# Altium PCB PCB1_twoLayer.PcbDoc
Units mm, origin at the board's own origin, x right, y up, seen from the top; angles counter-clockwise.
Board outline 70 x 67 mm, 2 copper layers (Top Layer, Bottom Layer), stack 1.569 mm thick; 44 components, 52 nets, 201 pads, 36 vias.
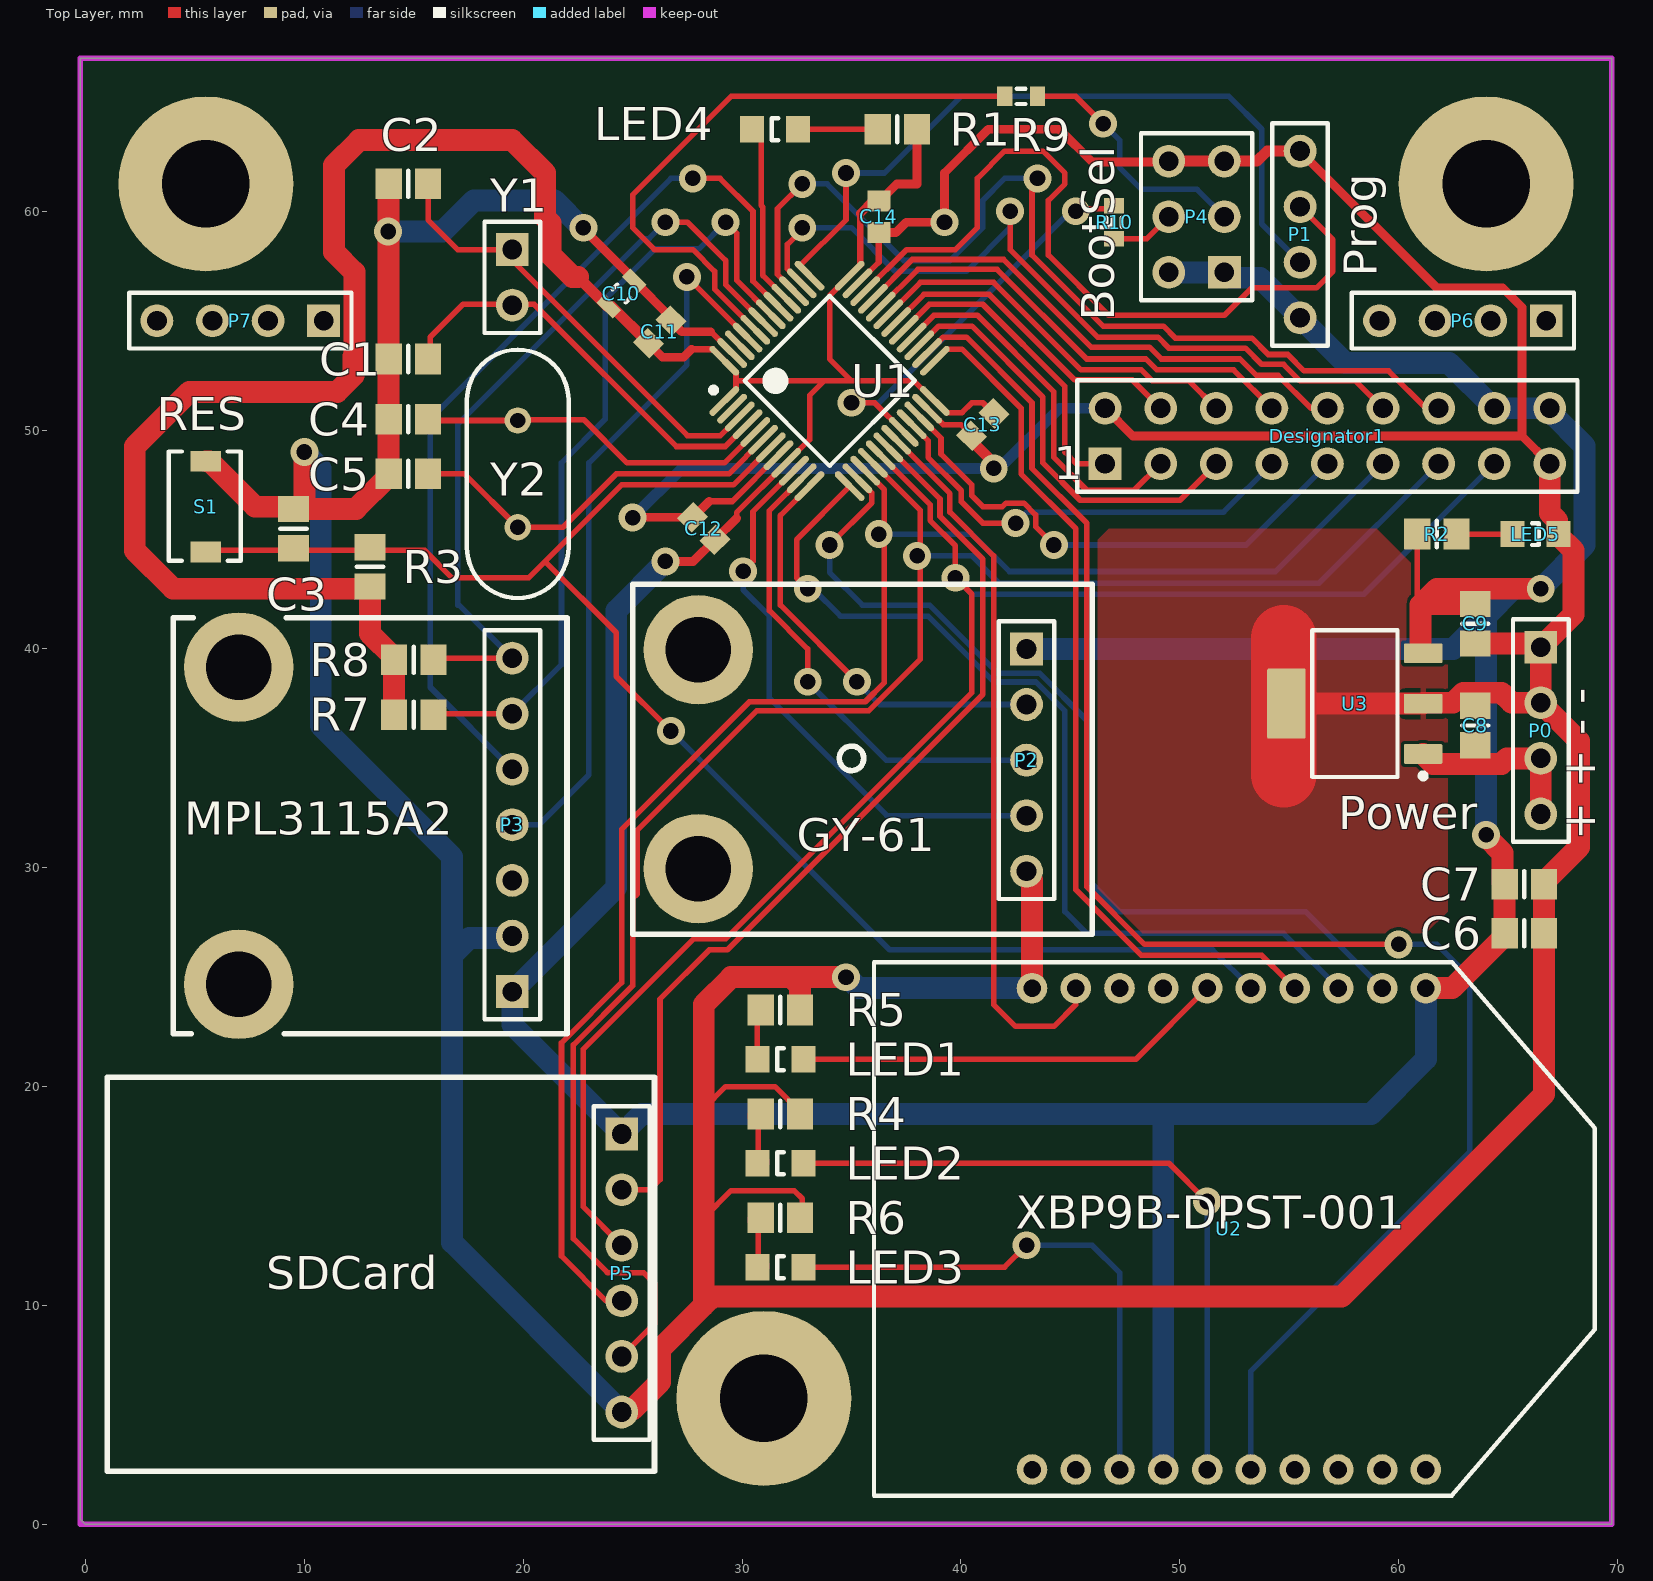
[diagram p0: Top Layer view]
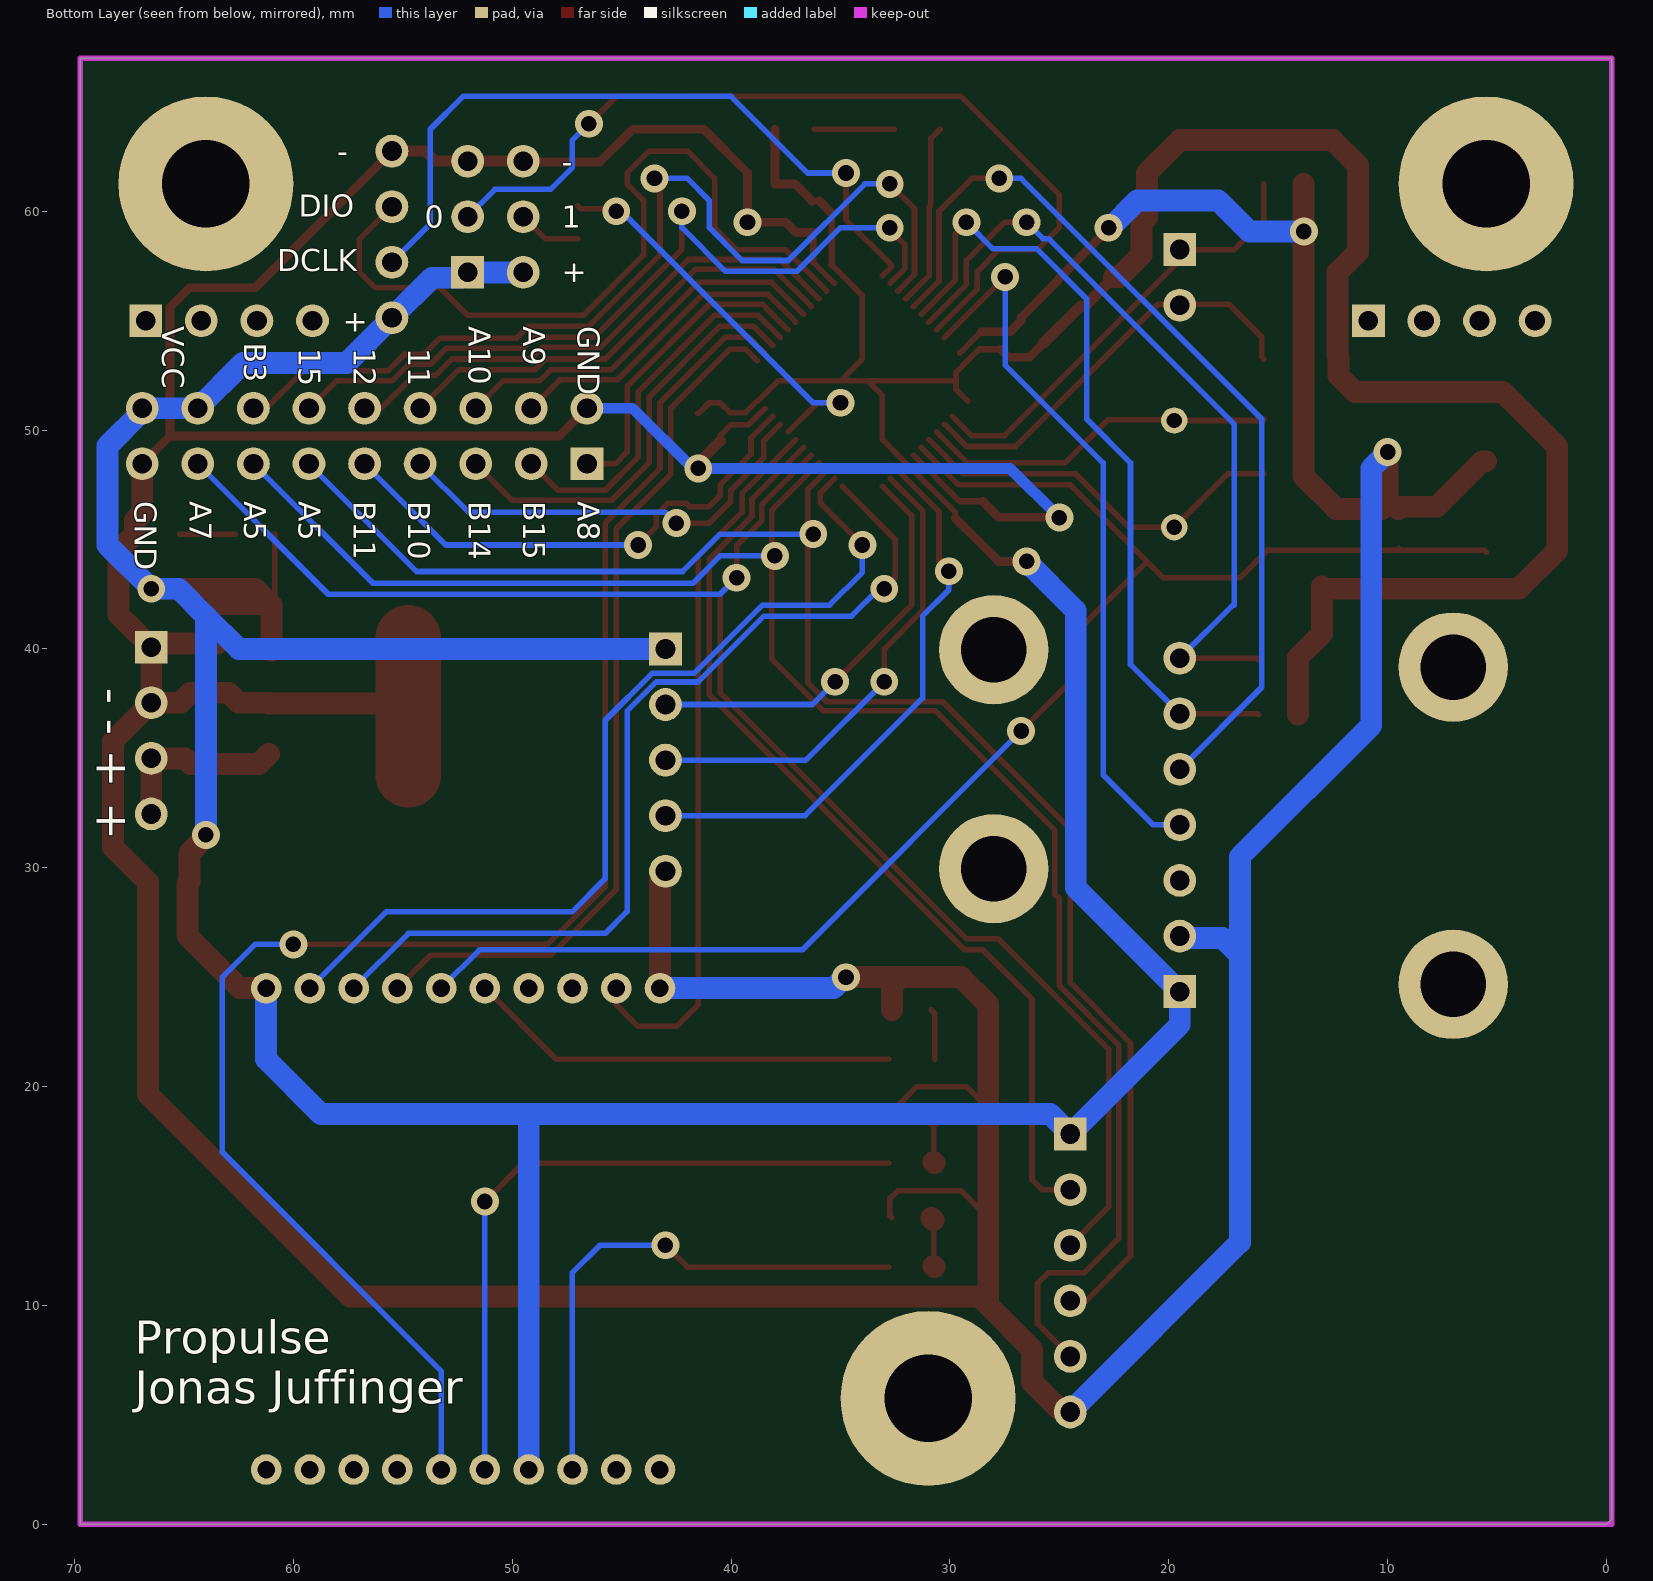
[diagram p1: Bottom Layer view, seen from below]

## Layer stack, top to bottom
Top Solder: solder mask 0.0254, SM-001, Dk 4
Top Layer: signal copper 0.035
Dielectric 1: core 1.4986, Core-043, Dk 4.3
Bottom Layer: signal copper 0.035
Bottom Solder: solder mask 0.0254, SM-001, Dk 4

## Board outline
0,0 -0.25,0.25 -0.25,67 69.75,67 69.75,0

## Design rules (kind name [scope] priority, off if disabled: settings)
Clearance [All] p1: gap=0.152 ignorepadtopadclearanceinfootprint=FALSE
HoleSize [All] p1: absolutevalues=TRUE maxlimit=6 minlimit=0.025 maxpercent=80.000 minpercent=20.000
PolygonConnect [All] p1: connectstyle=Relief reliefconductorwidth=0.254 reliefentries=4 polygonreliefangle="90 Angle" airgapwidth=0.254
RoutingVias [All] p1: holewidth=0.711 width=1.27 viastyle="Through Hole" minholewidth=0.711 minwidth=1.27 maxholewidth=0.711 maxwidth=1.27
SilkToSilkClearance [All] p1: silktosilkclearance=0
SilkToSolderMaskClearance [IsPad] p1: minsilkscreentomaskgap=0.15 clearancetoexposedcopper=TRUE
SolderMaskExpansion [All] p1: expansion=0.102
Width [All] p1: maxlimit=10 minlimit=0.254 preferedwidth=0.254
27 further rules are at their usual default settings.

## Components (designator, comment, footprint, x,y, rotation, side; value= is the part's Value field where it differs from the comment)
C1 "Cap" 6-0805_N 14.75,53.25 r180 top value=12pF
C2 "Cap" 6-0805_N 14.75,61.25 r180 top value=12pF
C3 "Cap" 6-0805_N 9.5,45.5 r270 top value=100nF
C4 "Cap" 6-0805_N 14.75,50.5 r0 top value=18pF
C5 "Cap" 6-0805_N 14.75,48 r0 top value=18pF
C6 "Cap" 6-0805_N 65.75,27 r180 top value=100nF
C7 "Cap" 6-0805_N 65.75,29.25 r180 top value=1µF
C8 "Cap" 6-0805_N 63.5,36.5 r270 top value=10uF
C9 "Cap" 6-0805_N 63.5,41.15 r90 top value=10uF
C10 "1 µF" CAPC1609X100X15NL20 24.487,56.237 r225 top
C11 "100 nF" SAMS-C0603-2_M 26.237,54.487 r45 top
C12 "100 nF" SAMS-C0603-2_M 28.25,45.5 r135 top
C13 "100 nF" SAMS-C0603-2_M 41,50.25 r225 top
C14 "100 nF" SAMS-C0603-2_M 36.25,59.75 r270 top
Designator1 "Header 9X2" HDR2X9 46.59,48.46 r0 top (schematic designator "Designator 1")
LED1 "150080SS75000" 0805_A 31.75,21.25 r0 top
LED2 "150080SS75000" 0805_A 31.75,16.5 r0 top
LED3 "150080SS75000" 0805_A 31.75,11.75 r0 top
LED4 "150080SS75000" 0805_A 31.5,63.75 r0 top
LED5 "150080SS75000" 0805_A 66.25,45.25 r180 top
P0 "Power" HDR1X4#1 66.5,40.08 r270 top
P1 "Prog" HDR1X4#2 55.5,55.13 r90 top
P2 "GY-61" HDR1X5 43,40 r270 top
P3 "MPL3115A2" HDR1X7 19.5,24.34 r90 top
P4 "BootSel" HDR2X3 52.04,57.21 r90 top
P5 "SDCard" HDR1X6 24.5,17.83 r270 top
P6 "Breadboard Mount" HDR1X4#1 66.75,55 r180 top
P7 "Breadboard Mount" HDR1X4#1 10.88,55 r180 top
R1 "Res1" 6-0805_N 37.1,63.75 r0 top value=1K
R2 "Res1" 6-0805_N 61.75,45.25 r180 top value=1K
R3 "Res1" 6-0805_N 13,43.75 r270 top value=10k
R4 "Res1" 6-0805_N 31.75,18.75 r180 top value=1K
R5 "Res1" 6-0805_N 31.75,23.5 r180 top value=1K
R6 "Res1" 6-0805_N 31.75,14 r180 top value=1K
R7 "Res1" 6-0805_N 15,37 r180 top value=2K
R8 "Res1" 6-0805_N 15,39.5 r180 top value=2K
R9 "Res3" J1-0603 42.75,65.25 r0 top value=100K
R10 "Res3" J1-0603 47,59.5 r90 top value=100K
S1 "RES" "SWITCH- TL1015AF160QG" 5.5,46.5 r90 top
U1 "STM32F103C8T6" STM-LQFP48_N 34,52.25 r45 top
U2 "XBP9B-DPST-001" DIP2200W51P200L3294H279Q20P 52.5,13.5 r270 top
U3 "TL1963A-33DCYR" DCY0004A_N 58,37.5 r180 top
Y1 "XTAL" HDR1X2 19.5,58.25 r270 top
Y2 "FOXSLF/120-20" FOX-FOXSLF-2_V 19.75,48 r270 top

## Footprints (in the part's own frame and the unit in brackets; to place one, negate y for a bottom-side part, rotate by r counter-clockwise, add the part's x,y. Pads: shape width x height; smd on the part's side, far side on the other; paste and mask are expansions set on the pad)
6-0805_N [mm] "Chip Resistor, Body 2.0x1.2mm, IPC Medium Density"
  rect 1.2x1.4 smd: 1(-0.9,0) 2(0.9,0)
  silkscreen extent 0,-0.6 0,0.6, body extent -1.07,-0.7 1.07,0.7, height 0.7
0805_A [mm] "Chip LED, 2-Leads, Body 2.0x1.3mm, IPC Medium Density"
  rect 1.1x1.2 smd: 1(-1.05,0) 2(1.05,0)
  silkscreen extent -0.15,-0.5 0.15,0.5, body extent -1,-0.62 1,0.63, height 0.68
CAPC1609X100X15NL20 [mm] "Chip Capacitor, 2-Leads, Body 1.60x0.85mm, IPC Medium Density"
  rect 0.55x1.05 smd: 1(-0.825,0) 2(0.825,0)
  silkscreen extent -0.15,-0.42 0.15,0.42, body extent -0.9,-0.53 0.9,0.53, height 1
DCY0004A_N [mm] "SOT223, 4-Leads, Body 6.7x3.7mm, Pitch 2.3mm, IPC Medium Density"
  rrect11% 1.75x0.9 smd: 1(-3.125,2.3) 2(-3.125,0) 3(-3.125,-2.3)
  rrect6% 1.75x3.2 smd: 4(3.125,0)
  silkscreen extent -3.25,-3.35 1.95,3.42, body extent -3.5,-3.25 3.5,3.25, height 1.62
DIP2200W51P200L3294H279Q20P [mm]
  round 1.4 hole 0.8: 1(-11,8.75) 2(-11,6.75) 3(-11,4.75) 4(-11,2.75) 5(-11,0.75) 6(-11,-1.25) 7(-11,-3.25) 8(-11,-5.25) 9(-11,-7.25) 10(-11,-9.25) 11(11,-9.25) 12(11,-7.25) 13(11,-5.25) 14(11,-3.25) 15(11,-1.25) 16(11,0.75) 17(11,2.75) 18(11,4.75) 19(11,6.75) 20(11,8.75)
  silkscreen extent -12.19,-16.47 12.19,16.47, body extent -12.18,-16.77 12.2,16.17, height 4.09
FOX-FOXSLF-2_V [mm] "THD, 2-Leads, Body 11.35x4.65mm, Pitch 4.88mm"
  round 1.2 hole 0.7: 1(-2.44,0) 2(2.44,0)
  silkscreen extent -5.68,-2.32 5.68,2.32, body extent -5.67,-2.32 5.68,2.32, height 3.6
HDR1X2 [mm] "Connector; Header; 2 Position"
  rect 1.5x1.5 hole 0.9: 1(0,0)
  round 1.5 hole 0.9: 2(2.54,0)
  silkscreen extent -1.27,-1.27 3.81,1.27
HDR1X4#1 [mm] "Connector; Header; 4 Position"
  rect 1.5x1.5 hole 0.9: 1(0,0)
  round 1.5 hole 0.9: 2(2.54,0) 3(5.08,0) 4(7.62,0)
  silkscreen extent -1.27,-1.27 8.89,1.27
HDR1X4#2 [mm] "Connector; Header; 4 Position"
  round 1.5 hole 0.9: 1(0,0) 2(2.54,0) 3(5.08,0) 4(7.62,0)
  silkscreen extent -1.27,-1.27 8.89,1.27
HDR1X5 [mm] "Connector; Header; 5 Position"
  rect 1.5x1.5 hole 0.9: 1(0,0)
  round 1.5 hole 0.9: 2(2.54,0) 3(5.08,0) 4(7.62,0) 5(10.16,0)
  silkscreen extent -1.27,-1.27 11.43,1.27
HDR1X6 [mm] "Connector; Header; 6 Position"
  rect 1.5x1.5 hole 0.9: 1(0,0)
  round 1.5 hole 0.9: 2(2.54,0) 3(5.08,0) 4(7.62,0) 5(10.16,0) 6(12.7,0)
  silkscreen extent -1.27,-1.27 13.97,1.27
HDR1X7 [mm] "Connector; Header; 7 Position"
  rect 1.5x1.5 hole 0.9: 1(0,0)
  round 1.5 hole 0.9: 2(2.54,0) 3(5.08,0) 4(7.62,0) 5(10.16,0) 6(12.7,0) 7(15.24,0)
  silkscreen extent -1.27,-1.27 16.51,1.27
HDR2X3 [mm] "Connector; Header; 3x2 Position"
  rect 1.5x1.5 hole 0.9: 1(0,0)
  round 1.5 hole 0.9: 2(0,2.54) 3(2.54,0) 4(2.54,2.54) 5(5.08,0) 6(5.08,2.54)
  silkscreen extent -1.27,-1.27 6.35,3.81
HDR2X9 [mm] "Connector; Header; 9x2 Position"
  rect 1.5x1.5 hole 0.9: 1(0,0)
  round 1.5 hole 0.9: 2(0,2.54) 3(2.54,0) 4(2.54,2.54) 5(5.08,0) 6(5.08,2.54) 7(7.62,0) 8(7.62,2.54) 9(10.16,0) 10(10.16,2.54) 11(12.7,0) 12(12.7,2.54) 13(15.24,0) 14(15.24,2.54) 15(17.78,0) 16(17.78,2.54) 17(20.32,0) 18(20.32,2.54)
  silkscreen extent -1.27,-1.27 21.59,3.81
J1-0603 [mm] "Chip Resistor, Body 1.6x0.8mm, IPC High Density"
  rect 0.7x0.9 smd: 1(-0.75,0) 2(0.75,0)
  silkscreen extent -0.2,-0.35 0.2,0.35, body extent -0.85,-0.48 0.85,0.48, height 0.9
SAMS-C0603-2_M [mm] "Chip Capacitor, 2-Leads, Body 1.70x0.90mm, IPC Low Density"
  rect 0.95x1.05 smd: 1(-0.725,0) 2(0.725,0)
  body extent -0.85,-0.45 0.85,0.45, height 0.9
STM-LQFP48_N [mm] "QFP, 48-Leads, Body 7x7mm, Pitch 0.5mm, IPC Medium Density"
  oval 1.8x0.3 smd: 1(-4.05,2.75) 2(-4.05,2.25) 3(-4.05,1.75) 4(-4.05,1.25) 5(-4.05,0.75) 6(-4.05,0.25) 7(-4.05,-0.25) 8(-4.05,-0.75) 9(-4.05,-1.25) 10(-4.05,-1.75) 11(-4.05,-2.25) 12(-4.05,-2.75) 25(4.05,-2.75) 26(4.05,-2.25) 27(4.05,-1.75) 28(4.05,-1.25) 29(4.05,-0.75) 30(4.05,-0.25) 31(4.05,0.25) 32(4.05,0.75) 33(4.05,1.25) 34(4.05,1.75) 35(4.05,2.25) 36(4.05,2.75)
  oval 0.3x1.8 smd: 13(-2.75,-4.05) 14(-2.25,-4.05) 15(-1.75,-4.05) 16(-1.25,-4.05) 17(-0.75,-4.05) 18(-0.25,-4.05) 19(0.25,-4.05) 20(0.75,-4.05) 21(1.25,-4.05) 22(1.75,-4.05) 23(2.25,-4.05) 24(2.75,-4.05) 37(2.75,4.05) 38(2.25,4.05) 39(1.75,4.05) 40(1.25,4.05) 41(0.75,4.05) 42(0.25,4.05) 43(-0.25,4.05) 44(-0.75,4.05) 45(-1.25,4.05) 46(-1.75,4.05) 47(-2.25,4.05) 48(-2.75,4.05)
  silkscreen extent -4.17,-2.75 2.75,3.57, body extent -3.5,-3.5 3.5,3.5, height 1.6
"SWITCH- TL1015AF160QG" [mm]
  rect 0.95x1.4 smd: 1(-2.075,0) 2(2.075,0)
  silkscreen extent -2.47,-1.6 2.53,1.7, body extent -2.26,-1.4 2.24,1.5, height 2.05

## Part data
C1 C2 C3 C4 C5 C6 C7 C8 C9: "Capacitor"
C10: library part CMP-2006-00184-1, Manufacturer="AVX Interconnect / Elco", Part Number=TACL105K010XTA
C11 C12 C13 C14: library part CMP-2000-05332-1, "Multi-layer Ceramic Capacitor, -55 to 125 degC, 2-Pin SMD (0603), RoHS, Tape and Reel", Capacitance=0.1µF, Case Size/Dimension=0603, Dielectric=X7R, Manufacturer="Samsung Electro-Mechanics", Rated Voltage=50V, Tolerance (%)=±10%
Designator1: "Header, 9-Pin, Dual row"
LED1 LED2 LED3 LED4 LED5: library part CMP-1426-00010-1, "SMD mono-color Chip LED, WL-SMCW, Super Red", Color="Super Red", Manufacturer="Wuerth Elektronik"
P0 P6 P7: library part "Header 4", "Header, 4-Pin"
P1: library part "Header 4", "Programming header like on Blue Pill"
P2: library part "Header 5", "GY-61 breakout board"
P3: library part "Header 7", "Adafruit MPL3115A2 breakout board"
P4: library part "Header 3X2", "Header, 3-Pin, Dual row"
P5: library part "Header 6", "Header, 6-Pin"
R1 R2 R3 R4 R5 R6 R7 R8 R9 R10: "Resistor"
S1: library part SWITCH_2PIN, Supplier Part Number 1=2292962
U1: "ARM Cortex-M3 32-bit MCU, 64 KB Flash, 20 KB Internal RAM, 37 I/Os, 48-pin LQFP, -40 to 85 degC, Tray", I/Os (High Current)=37, Operating Frequency(F) (Processor speed) (MHz)=72, Supplier Part Number 1=497-6063-ND, Supply Voltage(Vcc) min (V)=2
U2: "XBee-PRO 900HP _S3B_ Point2Multipoint, 900MHz, 250mW, RPSMA, 10Kbps", Package="Module Digi International"
U3: library part CMP-0395-00535-2, "Single Output Low Noise LDO, 1.5 A, Fixed 3.3 V Output, 2.1 to 20 V Input, 4-pin SOT-223 (DCY), -40 to 125 degC, Green (RoHS & no Sb/Br)", Manufacturer="Texas Instruments"
Y1: "Crystal Oscillator"
Y2: library part CMP-1749-00004-1, "Resistance Weld Thru-Hole Crystal, 12 MHz, +/-30 ppm, -20 to 70 degC, 2-Pin THD, RoHS, Bulk", Case\Package=TO-251-3, Input Capacitance="350 pF", Max Operating Temperature="150 degC", Max Power Dissipation="2.5 W", Min Operating Temperature="-55 degC", Package Quantity=70

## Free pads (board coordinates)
  round 5 hole 3: 1(28,29.96) 1(28,39.96) 2(7,24.67) 2(7,39.17)
  round 8 hole 4: 3(5.5,61.25) 3(31,5.75) 3(64,61.25)

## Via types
v1: diameter 1.27, hole 0.711, Top Layer to Bottom Layer, 36 vias

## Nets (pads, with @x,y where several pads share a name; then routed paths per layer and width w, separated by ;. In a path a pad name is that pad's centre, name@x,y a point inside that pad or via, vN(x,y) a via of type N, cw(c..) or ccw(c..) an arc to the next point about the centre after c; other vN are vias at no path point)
AccX: P2.2 U1.12 | length 19.1
  Top Layer w0.254: U1.12 33.081,47.429 31.75,46.098 31.75,42 v1(35.25,38.5)
  Bottom Layer w0.254: v1(35.25,38.5) 36.29,37.46 P2.2
AccY: P2.3 U1.11 | length 22.1
  Top Layer w0.254: U1.11 31.25,46.318 31.25,41.75 33,40 v1(33,38.5)
  Bottom Layer w0.254: v1(33,38.5) 36.58,34.92 P2.3
AccZ: P2.4 U1.10 | length 25.8
  Top Layer w0.254: v1(30.047,43.547) 30.5,44 30.5,46.275 U1.10
  Bottom Layer w0.254: v1(30.047,43.547) 30.047,42.703 31.25,41.5 31.25,37.75 36.62,32.38 P2.4
BaroInt1: P3.5 U1.41 | length 42.3
  Top Layer w0.254: v1(27.75,61.5) 29,61.5 30.5,60 30.5,56.811 U1.41
  Bottom Layer w0.254: P3.5 15.75,38.25 15.75,50.5 26.75,61.5 v1(27.75,61.5)
BaroInt2: P3.4 U1.45 | length 33
  Top Layer w0.254: v1(27.482,57) U1.45
  Bottom Layer w0.254: P3.4 20.71,31.96 23,34.25 23,48.5 27.482,52.982 v1(27.482,57)
BOOT0: R9.1 U1.44 | length 28.4
  Top Layer w0.254: U1.44 28.75,56.439 28.75,57.25 27.75,58.25 26,58.25 25,59.25 25,60.75 29.5,65.25 R9.1
BOOT1: R10.2 U1.20 | length 18.7
  Top Layer w0.254: v1(35,51.25) 36.061,51.25 U1.20 ; v1(45.25,60) 45.375,60.125 46.875,60.125 R10.2
  Bottom Layer w0.254: v1(35,51.25) 36.25,51.25 45,60 v1(45.25,60)
DCLK: P1.2 U1.37 | length 33.6
  Top Layer w0.254: U1.37 32.655,57.484 32.655,57.514 34.75,59.609 v1(34.75,61.75)
  Bottom Layer w0.254: v1(34.75,61.75) 36.5,61.75 40,65.25 52.25,65.25 53.75,63.75 53.75,59.42 P1.2
DIO: P1.3 U1.34 | length 36.1
  Top Layer w0.254: U1.34 37.525,58.25 39.75,58.25 40.75,59.25 40.75,61.5 42,62.75 43.75,62.75 44.75,61.75 44.75,61.25 44,60.5 44,58 46.75,55.25 52.042,55.25 53.292,56.5 56.25,56.5 57,57.25 57,58.71 P1.3
GND: C1.2 C2.2 C3.1 C4.1 C5.1 C6.1 C7.1 C8.1 C9.1 C10.1 C11.2 C12.2 C13.2 C14.2 Designator1.2 Designator1.17 LED5.1 P0.1 P0.2 P1.4 P2.5 P3.2 P4.5 P4.6 P5.6 R4.1 R5.1 R6.1 S1.2 U1.8 U1.23 U1.35 U1.47 U2.10 U3.2 U3.4 | length 350
  Top Layer w0.254: v1@22.75,59.196 v1(22.75,59.25) ; P5.6 P5.6@24.614,5.244 ; v1(25,46) v1@25.013,46.013 ; C10.1 C10.1@25.071,56.875 ; C11.2 C11.2@26.75,55.141 ; C12.2 C12.2@27.763,46.013 ; 28.25,14 29.5,15.25 32.378,15.25 32.75,14.878 32.75,14.1 R6.1 ; 28.25,19 29.25,20 31.5,20 32.65,18.85 R4.1 ; 28.568,54.5 U1.47 ; 29.561,46.75 U1.8 ; U1.35 36.25,57.682 ; U1.23@38.442,50.977 U1.23 38.467,50.977 39.194,50.25 40,50.25 40.487,49.763 C13.2 C13.2@40.487,49.513 ; U3.2 U3.2@61.165,37.54 ; C7.1 C7.1@66.65,29.35 ; LED5.1@67.25,45.2 LED5.1@67.3,45.2
  Top Layer w0.3: 28.5,46.75 29.561,46.75 ; 36.25,57.682 C14.2
  Top Layer w0.4: v1@22.75,59.196 C10.1@25.071,56.875 ; v1@25.013,46.013 C12.2 ; C10.1 C11.2@26.75,55.141 ; C11.2 27.25,54.5 28.568,54.5 ; C12.2@27.763,46.013 28.5,46.75 ; C14.2 37.025,59.025 37.5,59.5 v1(39.25,59.5) 39.25,61.75 41.25,63.75 44.5,63.75 46,62.25 49.46,62.25 P4.6 ; Designator1.2 47.86,49.73 65.64,49.73 ; P1.4 61.75,56.5 64.75,56.5 65.64,55.61 65.64,49.73 ; Designator1.17 65.64,49.73
  Top Layer w0.5: C3.1 C3.1@9.5,46.75 ; v1(13.825,59.075) v1@13.838,59.063 ; C1.2@13.838,53.263 C1.2 ; C13.2@40.487,49.513 41.5,48.5 v1(41.5,48.25) ; P4.6 P4.5 53.54,62.29 54,62.75 P1.4
  Top Layer w1: S1.2 5.675,48.575 7.75,46.5 9.4,46.5 C3.1 ; v1(10,49) 10,46.65 10.25,46.4 12.35,46.4 13.85,47.9 C5.1 C4.1 C1.2 ; v1(13.825,59.075) 13.838,59.088 13.838,61.238 C2.2 ; C1.2@13.838,53.263 v1@13.838,59.063 ; P5.6@24.614,5.244 24.994,5.244 26.25,6.5 26.25,8 28.25,10 ; R5.1 32.65,24.6 32.25,25 ; v1(34.75,25) 32.25,25 ; P2.5 43,29.705 43.25,29.455 U2.10 ; U3.4 U3.2 ; U3.2@61.125,37.54 61.165,37.54 62.499,37.54 62.959,38 64.706,38 65.166,37.54 P0.2 ; C9.1 P0.1@66.5,40.25 ; C7.1 C6.1 66.65,19.65 57.402,10.402 28.652,10.402 28.25,10 ; C7.1@66.65,29.35 68.25,30.95 68.25,35.79 P0.2 ; Designator1.17 66.91,46.21 67.25,45.87 67.25,45.3 LED5.1 LED5.1@67.25,45.2 ; LED5.1@67.3,45.2 68,44.5 68,41.58 P0.1 P0.2 ; 28.25,10 28.25,14 28.25,19 28.25,23.75 29.5,25 32.25,25
  Top Layer w3: 54.75,34.25 54.75,40.5
  Bottom Layer w0.5: v1(25,46) 27.25,48.25 v1(41.5,48.25) 41.75,48.25 44.5,51 Designator1.2
  Bottom Layer w1: v1(10,49) 10.75,48.25 10.75,36.5 16.75,30.5 16.75,26 17.534,26.784 19.404,26.784 P3.2 ; v1(13.825,59.075) 16.325,59.075 17.75,60.5 21.427,60.5 22.677,59.25 v1(22.75,59.25) ; 16.75,25.914 16.75,12.88 P5.6 ; v1(34.75,25) 34.823,25 35.323,24.5 U2.10
MISO: Designator1.13 P5.5 U1.16 | length 81
  Top Layer w0.254: P5.5 26,9.17 26,11 25.5,11.5 23.852,11.5 22.296,13.056 22.296,21.904 25,24.608 25,28.588 25.221,28.809 25.221,31.721 30.679,37.179 35.797,37.179 38.138,39.52 38.138,46.344 U1.16
  Bottom Layer w0.254: v1(38,44.25) 40.5,44.25 41.75,43 56.37,43 Designator1.13
MOSI: Designator1.15 P5.3 U1.17 | length 74.2
  Top Layer w0.254: P5.3 22.75,14.5 22.75,21.716 27.784,26.75 29.25,26.75 40.5,38 40.5,42.5 v1(39.75,43.25) 39.75,44.716 38.592,45.874 38.592,46.597 U1.17
  Bottom Layer w0.254: v1(39.75,43.25) 40.5,42.5 58.41,42.5 Designator1.15
NetC8_2: C8.2 P0.3 P0.4 U3.1 | length 8.2
  Top Layer w1: U3.1 61.575,34.75 64.7,34.75 64.95,35 P0.3 P0.4
NetLED1_1: LED1.1 R5.2 | length 2.3
  Top Layer w0.254: LED1.1 30.7,23.35 R5.2
NetLED1_2: LED1.2 U2.6 | length 19.8
  Top Layer w0.254: LED1.2 48,21.25 U2.6
NetLED2_1: LED2.1 R4.2 | length 2.3
  Top Layer w0.254: LED2.1@30.75,16.55 R4.2@30.75,18.65
  Top Layer w1: LED2.1 LED2.1@30.75,16.55 ; R4.2@30.75,18.65 R4.2
NetLED2_2: LED2.2 U2.15 | length 31.4
  Top Layer w0.254: LED2.2 49.5,16.5 v1(51.25,14.75)
  Bottom Layer w0.254: U2.15 v1(51.25,14.75)
NetLED3_1: LED3.1 R6.2 | length 2.3
  Top Layer w0.254: LED3.1@30.75,11.8 R6.2@30.75,13.9
  Top Layer w1: LED3.1 LED3.1@30.75,11.8 ; R6.2@30.75,13.9 R6.2
NetLED3_2: LED3.2 U2.13 | length 24.4
  Top Layer w0.254: LED3.2 42,11.75 v1(43,12.75)
  Bottom Layer w0.254: v1(43,12.75) 46,12.75 47.25,11.5 U2.13
NetLED4_2: LED4.2 R1.1 | length 3.7
  Top Layer w0.254: LED4.2 R1.1
NetLED5_2: LED5.2 R2.1 | length 2.6
  Top Layer w0.254: R2.1 LED5.2
NetP4_3: P4.3 R9.2 | length 11.6
  Top Layer w0.254: R9.2 45.25,65.25 v1(46.5,64)
  Bottom Layer w0.254: v1(46.5,64) 47.25,63.25 47.25,62 48.25,61 50.79,61 P4.3
NetP4_4: P4.4 R10.1 | length 2.9
  Top Layer w0.254: R10.1 48.5,58.75 P4.4
NRST: C3.2 R3.1 S1.1 U1.7 U2.5 | length 70.5
  Top Layer w0.254: S1.1 5.575,44.5 C3.2@9.4,44.5 ; C3.2 C3.2@9.4,44.5 ; v1(26.75,36.25) 24.25,38.75 24.25,40.75 21,44 ; U1.7 29.604,47.5 24.5,47.5 21,44 ; C3.2@9.4,44.5 9.5,44.5 15.5,44.5 16.75,43.25 20.25,43.25 21,44
  Bottom Layer w0.254: v1(26.75,36.25) 36.75,26.25 51.5,26.25 U2.5
PA8: Designator1.1 U1.29 | length 14.5
  Top Layer w0.254: U1.29 38.561,55.75 41,55.75 44.75,52 44.75,49 45.29,48.46 Designator1.1
PA11: Designator1.8 U1.32 | length 21.2
  Top Layer w0.254: U1.32 38.031,57.342 41.658,57.342 45.75,53.25 48.454,53.25 48.954,52.75 52.46,52.75 Designator1.8
PA12: Designator1.10 U1.33 | length 24.3
  Top Layer w0.254: U1.33 37.778,57.796 41.954,57.796 45.954,53.796 48.612,53.796 49.158,53.25 52.75,53.25 53.5,52.5 54.5,52.5 56,51 Designator1.10
PA15: Designator1.12 U1.38 | length 36.8
  Top Layer w0.254: U1.38 32.727,56.717 32.073,57.371 32.073,58.49 32.75,59.166 v1(32.75,59.25) ; v1(42.25,60) 42.25,58.25 46.25,54.25 49,54.25 49.5,53.75 53,53.75 53.75,53 54.75,53 55.5,52.25 58.04,52.25 Designator1.12
  Bottom Layer w0.254: v1(32.75,59.25) 35,59.25 37,57.25 40.25,57.25 42.25,59.25 v1(42.25,60)
PB3: Designator1.14 U1.39 | length 45.2
  Top Layer w0.254: U1.39 32.374,56.364 31.619,57.118 31.619,60.119 v1(32.75,61.25) ; v1(43.5,61.5) 43.25,61.25 43.25,58 46.5,54.75 49.25,54.75 49.796,54.204 53.296,54.204 54.046,53.454 54.938,53.454 55.688,52.704 59.546,52.704 61.25,51 Designator1.14
  Bottom Layer w0.254: v1(32.75,61.25) 33.89,61.25 37.39,57.75 39.5,57.75 41,59.25 41,60.5 42,61.5 v1(43.5,61.5)
PB4: LED4.1 U1.40 | length 8.4
  Top Layer w0.254: LED4.1 30.873,63.327 30.873,60.269 30.954,60.188 30.954,57.064 U1.40
PB9: U1.46
PB14: Designator1.5 U1.27 | length 19.7
  Top Layer w0.254: U1.27 38.114,53.876 38.987,54.75 40.5,54.75 43.75,51.5 43.75,48.5 45.454,46.796 50.006,46.796 Designator1.5
PB15: Designator1.3 U1.28 | length 17.4
  Top Layer w0.254: U1.28 38.768,55.25 40.75,55.25 44.25,51.75 44.25,48.75 45.75,47.25 47.92,47.25 Designator1.3
PC0: C4.2 U1.5 Y2.1 | length 16.4
  Top Layer w0.254: C4.2 15.71,50.44 Y2.1 19.793,50.483 22.767,50.483 24.75,48.5 29.189,48.5 U1.5
PC1: C5.2 U1.6 Y2.2 | length 18
  Top Layer w0.254: C5.2 17.31,48 Y2.2 21.81,45.56 24.25,48 29.396,48 U1.6
PC13: U1.2
PC14: C2.1 U1.3 Y1.1 | length 20.3
  Top Layer w0.254: C2.1 15.65,59.6 17,58.25 19,58.25 27.5,49.75 29.013,49.75 29.886,50.624 U1.3
PC15: C1.1 U1.4 Y1.2 | length 19.3
  Top Layer w0.254: C1.1 15.75,53.35 15.75,54.25 17.25,55.75 20.5,55.75 27,49.25 29.232,49.25 U1.4
RADIO_CTS: U1.25 U2.4 | length 40.4
  Top Layer w0.254: U1.25 39.339,53.7 40.05,53.7 42.75,51 42.75,48 45.25,45.5 45.25,29 48.25,26 53.75,26 54.825,24.925 55.25,24.925 U2.4
RADIO_RTS: U1.26 U2.16 | length 75.3
  Top Layer w0.254: U1.26 38.467,53.523 39.194,54.25 40.25,54.25 43.25,51.25 43.25,48.25 45.75,45.75 45.75,29.142 48.392,26.5 v1(60,26.5)
  Bottom Layer w0.254: U2.16 53.25,7 63.25,17 63.25,25 61.75,26.5 v1(60,26.5)
RADIO_SLEEP: U1.19 U2.9 | length 33.2
  Top Layer w0.254: U1.19 39.5,47.104 39.5,46.25 41.5,44.25 41.5,23.75 42.5,22.75 44.25,22.75 45.25,23.75 U2.9 U2.9@45.25,24.75
RX1: Designator1.6 U1.31 | length 18
  Top Layer w0.254: U1.31 38.146,56.75 41.5,56.75 45.495,52.755 48.245,52.755 48.75,52.25 50.42,52.25 Designator1.6
RX2: U1.14 U2.2 | length 42.7
  Top Layer w0.254: v1(34,44.75) 35.927,46.677 35.927,47.129 35.273,47.783 U1.14
  Bottom Layer w0.254: v1(34,44.75) 34,43.5 35.5,42 38.575,42 41.679,38.896 43.595,38.896 45.75,36.741 45.75,29.5 47.25,28 55.75,28 U2.2
RX3: Designator1.9 U1.22 | length 23.8
  Top Layer w0.254: U1.22 39.091,49.634 39.091,48.909 40.5,47.5 40.5,47 41,46.5 41.896,46.5 42.06,46.664 42.879,46.664 43.414,46.129 43.414,45.586 v1(44.25,44.75)
  Bottom Layer w0.254: v1(44.25,44.75) 53.04,44.75 Designator1.9
SCL: P3.6 R7.1 U1.42 | length 36.4
  Top Layer w0.254: R7.1 15.94,37.04 P3.6 ; v1(29.25,59.5) 29.75,59 29.75,56.854 U1.42
  Bottom Layer w0.254: P3.6 21.75,39.29 21.75,48.5 23.75,50.5 23.75,56 26.028,58.278 28.028,58.278 v1(29.25,59.5)
SD_CS: P5.2 U1.18 | length 43.8
  Top Layer w0.254: P5.2 25.79,15.29 26.25,15.75 26.25,24 28.5,26.25 29.325,26.25 41,37.925 41,44.108 39.046,46.062 39.046,46.85 U1.18
SDA: P3.7 R8.1 U1.43 | length 35.7
  Top Layer w0.254: R8.1 15.98,39.58 P3.7 ; v1(26.5,59.5) 27.5,59.5 29.25,57.75 29.25,56.646 U1.43
  Bottom Layer w0.254: 17,42 17,42.08 ; P3.7 17,42.08 ; v1(26.5,59.5) 25.75,58.75 25.5,58.75 17,50.25 17,42.08
SPI_CLK: Designator1.11 P5.4 U1.15 | length 74.9
  Top Layer w0.254: P5.4 23.79,10.21 21.75,12.25 21.75,22 24.5,24.75 24.5,31.75 30.336,37.586 35.629,37.586 36.5,38.457 36.5,47.275 U1.15
  Bottom Layer w0.254: v1(36.25,45.25) 40.5,45.25 42.212,43.538 54.368,43.538 Designator1.11
TX1: Designator1.4 U1.30 | length 14.8
  Top Layer w0.254: U1.30 38.308,56.204 41.296,56.204 45.199,52.301 47.829,52.301 Designator1.4
TX2: U1.13 U2.3 | length 43.1
  Top Layer w0.254: v1(33,42.75) 32.5,43.25 32.5,45 34.919,47.419 U1.13
  Bottom Layer w0.254: v1(33,42.75) 33.25,42.75 34.5,41.5 38.5,41.5 41.511,38.489 43.426,38.489 44.75,37.166 44.75,28 45.75,27 54.75,27 U2.3
TX3: Designator1.7 U1.21 | length 20.2
  Top Layer w0.254: U1.21 38.5,49.518 38.5,48.75 40.018,47.232 40.018,46.732 41,45.75 v1(42.5,45.75)
  Bottom Layer w0.254: v1(42.5,45.75) 43,46.25 52,46.25 Designator1.7
VCC: C6.2 C7.2 C9.2 C10.2 C11.1 C12.1 C13.1 C14.1 Designator1.16 Designator1.18 P1.1 P2.1 P3.1 P4.1 P4.2 P5.1 R1.2 R2.2 R3.2 R7.2 R8.2 U1.1 U1.9 U1.24 U1.36 U1.48 U2.1 U2.14 U3.3 | length 286.7
  Top Layer w0.254: R3.2@12.9,42.75 R3.2 ; R8.2 R8.2@14.1,39.6 ; C10.2@23.846,55.654 C10.2 C10.2@24.045,55.654 ; U1.48@28.661,53.7 U1.48 29.722,52.639 29.722,52.25 ; U1.1 29.722,51.861 29.722,52.25 ; 29.75,45.975 29.75,46.232 U1.9 33.086,49.568 33.086,51.586 33.75,52.25 ; U1.36@35.398,57.537 U1.36 34,56.139 34,53.25 35,52.25 ; C14.1@35.975,60.475 C14.1 C14.1@36.3,60.475 ; C13.1 41.487,50.763 41,51.25 40.5,51.25 40.05,50.8 39.339,50.8 U1.24 38.776,51.331 37.857,52.25 35,52.25 ; R2.2 60.85,42.15 61,42 61.05,42.05 ; U3.3@61,39.925 U3.3 ; C6.2@64.85,26.9 C6.2 ; 29.722,52.25 33.75,52.25 ; 33.75,52.25 35,52.25
  Top Layer w0.3: 27.69,53.7 U1.48@28.661,53.7 ; U1.36@35.398,57.537 35.398,59.898
  Top Layer w0.4: C11.1 26.365,53.334 27.324,53.334 27.69,53.7 ; v1(26.5,44) 27.775,44 C12.1 29.75,45.975 ; 35.398,59.898 C14.1@35.975,60.475 ; C14.1@36.3,60.475 37.075,61.25 38,61.25 R1.2
  Top Layer w0.5: 22.5,57 C10.2@23.846,55.654 ; C10.2@24.045,55.654 C11.1
  Top Layer w1: R3.2@12.9,42.75 4,42.75 2.25,44.5 2.25,49.25 4.75,51.75 11.5,51.75 12.25,52.5 12.25,53.375 12.282,53.407 12.282,57.218 11.355,58.145 11.355,62.105 12.5,63.25 19.5,63.25 21,61.75 21,59.707 21.25,59.457 21.25,58 22.25,57 22.5,57 ; R3.2 13,40.7 R8.2@14.1,39.6 ; R7.2 R8.2 ; U3.3@61,39.925 61,42 ; U2.1 62.45,24.5 C6.2@64.85,26.9 ; C9.2 61.05,42.05 61.75,42.75 v1(66.5,42.75) ; v1(64,31.5) 64,31.427 64.75,30.677 64.75,29.35 C7.2 C6.2
  Bottom Layer w1: v1(26.5,44) 24.25,41.75 24.25,29.09 P3.1 19.5,22.83 P5.1 25.42,18.75 49.25,18.75 ; P2.1 62.5,40 64,41.5 ; U2.14 49.25,17.83 49.25,18.75 ; P4.2 P4.1 52.29,56.96 53.67,56.96 P1.1 57.565,53.065 62.305,53.065 Designator1.16 Designator1.18 66.91,50.865 68.5,49.275 68.5,44.75 v1(66.5,42.75) 65.25,42.75 64,41.5 ; U2.1 61.25,21.25 58.75,18.75 49.25,18.75 ; v1(64,31.5) 64,41.5
pads on no net: P3.3 P6.1 P6.2 P6.3 P6.4 P7.1 P7.2 P7.3 P7.4 U2.7 U2.8 U2.11 U2.12 U2.17 U2.18 U2.19 U2.20

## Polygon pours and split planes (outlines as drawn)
GND on Top Layer (solid, pour order 10): 62.25,42.25 59,45.5 46.75,45.5 46.25,45 46.25,27 61.25,27 62.25,28
no net on Top Layer (solid, pour order 4): 51.5,38.75

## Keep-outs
Keep-Out Layer:
  lines w0.254: -0.25,0 69.75,0 69.75,67 -0.25,67 -0.25,0

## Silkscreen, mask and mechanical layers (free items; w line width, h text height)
Top Overlay:
  circle w0.254: c35,35 r0.559
  circle w0.254: c35,35 r0.559
  lines w0.254: 4.83,22.42 4,22.42 4,41.42 4.92,41.42 ; 9.08,22.42 22,22.42 22,41.42 9.17,41.42 ; 1,2.42 1,20.42 26,20.42 26,2.42 1,2.42 ; 25,26.96 46,26.96 46,42.96 25,42.96 25,26.96
  text "1" at 44.25,47.75 h1.52
  text "+ + - -" at 69,31.25 h1.52 r90
Bottom Overlay:
  text "-" at 58,62.25 h1
  text "-" at 47.75,61.75 h1
  text "DIO" at 59.75,59.75 h1
  text "1" at 47.75,59.25 h1
  text "0" at 54,59.25 h1
  text "DCLK" at 60.75,57.25 h1
  text "+" at 47.75,56.75 h1
  text "GND" at 47,54.75 h1 r90
  text "A9" at 49.5,54.75 h1 r90
  text "A10" at 52,54.75 h1 r90
  text "VCC" at 66,54.75 h1 r90
  text "+" at 57.75,54.5 h1
  text "B3" at 62.25,54 h1 r90
  text "11" at 54.75,53.75 h1 r90
  text "12" at 57.25,53.75 h1 r90
  text "15" at 59.75,53.75 h1 r90
  text "A8" at 47,46.75 h1 r90
  text "B15" at 49.5,46.75 h1 r90
  text "B14" at 52,46.75 h1 r90
  text "B10" at 54.75,46.75 h1 r90
  text "B11" at 57.25,46.75 h1 r90
  text "A5" at 59.75,46.75 h1 r90
  text "A5" at 62.25,46.75 h1 r90
  text "A7" at 64.75,46.75 h1 r90
  text "GND" at 67.25,46.75 h1 r90
  text "+ + - -" at 69,31.25 h1.52 r90
  text "Propulse / Jonas Juffinger" at 67.25,5.5 h1.52
Mechanical 1:
  lines w0.254: -0.25,0 0,0 69.75,0 69.75,67 -0.25,67 -0.25,0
